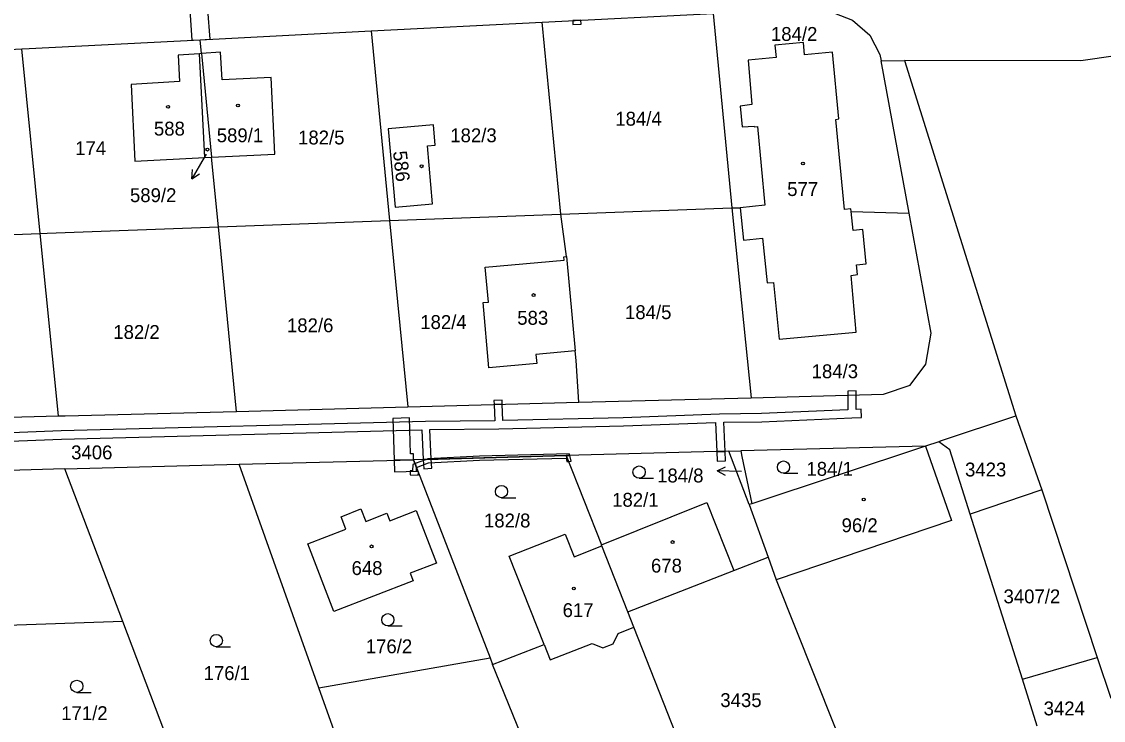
# Model space of a CAD drawing. Extents: x -776734 to -748832, y -1118122 to -976986.
# Drawn here: x -753177.2 to -753044.6, y -1115523.5 to -1115437.8 of the extents above; entities that cross this region are included whole.
import ezdxf

# ---------------------------------------------------------------- set-up
doc = ezdxf.new("R2010")
doc.units = 0
for name, color, linetype in [('KM_Hranice parcel', 7, 'Continuous'), ('KM_Parcelní čísla', 7, 'Continuous'), ('KM_Pop  PČ popisy', 7, 'Continuous'), ('KM_Vnitřní kresba', 7, 'Continuous'), ('KM_Věcná břemena k části', 7, 'Continuous'), ('KM_Značky budov', 7, 'Continuous'), ('KM_Značky kultur', 7, 'Continuous')]:
    doc.layers.add(name, color=color, linetype=linetype)

msp = doc.modelspace()

# ---------------------------------------------------------------- linework, layer by layer
at = {"layer": 'KM_Hranice parcel'}
for p, q in [((-753113.36, -1115437.88), (-753092.39, -1115436.81)), ((-753092.39, -1115436.81), (-753090.09, -1115460.62)), ((-753134.33, -1115438.96), (-753113.36, -1115437.88)), ((-753111.08, -1115461.4), (-753113.36, -1115437.88)), ((-753155.3, -1115440.03), (-753134.33, -1115438.96)), ((-753134.33, -1115438.96), (-753132.07, -1115462.19)), ((-753155.13, -1115441.73), (-753155.3, -1115440.03)), ((-753174.89, -1115463.79), (-753177.13, -1115441.15)), ((-753155.13, -1115441.73), (-753155.38, -1115441.75)), ((-753154.7, -1115454.48), (-753155.38, -1115441.75)), ((-753155.13, -1115441.73), (-753153.89, -1115454.44)), ((-753071.8, -1115442.63), (-753068.92, -1115442.57)), ((-753068.37, -1115461.3), (-753071.8, -1115442.63)), ((-753068.92, -1115442.57), (-753055.28, -1115486.14)), ((-753154.7, -1115454.48), (-753153.89, -1115454.44)), ((-753153.05, -1115462.97), (-753153.89, -1115454.44)), ((-753111.08, -1115461.4), (-753090.09, -1115460.62)), ((-753090.09, -1115460.62), (-753089.08, -1115460.62)), ((-753090.09, -1115460.62), (-753087.75, -1115483.91)), ((-753153.05, -1115462.97), (-753132.07, -1115462.19)), ((-753132.07, -1115462.19), (-753111.08, -1115461.4)), ((-753132.07, -1115462.19), (-753129.84, -1115485.02)), ((-753110.37, -1115466.62), (-753111.08, -1115461.4)), ((-753075.47, -1115461.08), (-753068.37, -1115461.3)), ((-753150.83, -1115485.58), (-753153.05, -1115462.97)), ((-753172.67, -1115486.15), (-753174.89, -1115463.79)), ((-753110.37, -1115466.62), (-753109.33, -1115478.16)), ((-753129.84, -1115485.02), (-753108.85, -1115484.47)), ((-753108.85, -1115484.47), (-753087.75, -1115483.91)), ((-753150.83, -1115485.58), (-753129.84, -1115485.02)), ((-753064.52, -1115489.21), (-753055.28, -1115486.14)), ((-753055.28, -1115486.14), (-753052.1, -1115495.21)), ((-753194.82, -1115486.74), (-753172.67, -1115486.15)), ((-753066.38, -1115489.83), (-753088.99, -1115490.44)), ((-753066.38, -1115489.83), (-753087.67, -1115496.9)), ((-753064.73, -1115489.32), (-753066.38, -1115489.83)), ((-753064.73, -1115489.32), (-753064.52, -1115489.21)), ((-753110.4, -1115491.01), (-753129.13, -1115491.51)), ((-753090.47, -1115490.48), (-753110.4, -1115491.01)), ((-753110.4, -1115491.01), (-753106.1, -1115501.92)), ((-753090.47, -1115490.48), (-753088.99, -1115490.44)), ((-753087.97, -1115497), (-753090.47, -1115490.48)), ((-753171.88, -1115492.64), (-753191.76, -1115493.16)), ((-753171.88, -1115492.64), (-753150.49, -1115492.07)), ((-753164.78, -1115511.33), (-753171.88, -1115492.64)), ((-753150.49, -1115492.07), (-753129.13, -1115491.51)), ((-753140.72, -1115519.45), (-753150.49, -1115492.07)), ((-753129.13, -1115491.51), (-753119.75, -1115515.79)), ((-753052.1, -1115495.21), (-753060.88, -1115498.18)), ((-753052.1, -1115495.21), (-753045.31, -1115515.73)), ((-753106.1, -1115501.92), (-753093.16, -1115496.77)), ((-753093.16, -1115496.77), (-753089.86, -1115505.08)), ((-753087.67, -1115496.9), (-753087.97, -1115497)), ((-753087.97, -1115497), (-753085.67, -1115503.45)), ((-753106.04, -1115502.07), (-753106.1, -1115501.92)), ((-753102.86, -1115510.15), (-753106.04, -1115502.07)), ((-753089.86, -1115505.08), (-753085.67, -1115503.45)), ((-753102.86, -1115510.15), (-753089.86, -1115505.08)), ((-753164.78, -1115511.33), (-753182.77, -1115511.96)), ((-753158.06, -1115529.01), (-753164.78, -1115511.33)), ((-753102.12, -1115512.03), (-753102.86, -1115510.15)), ((-753092.24, -1115537.11), (-753102.12, -1115512.03)), ((-753119.43, -1115516.62), (-753113.12, -1115514.16)), ((-753140.72, -1115519.45), (-753119.75, -1115515.79)), ((-753119.75, -1115515.79), (-753119.43, -1115516.62)), ((-753054.49, -1115518.4), (-753045.31, -1115515.73)), ((-753045.31, -1115515.73), (-753043.66, -1115520.72)), ((-753052.68, -1115524.15), (-753054.49, -1115518.4)), ((-753133.38, -1115540.03), (-753140.72, -1115519.45))]:
    msp.add_line(p, q, dxfattribs=at)
for points in [[(-753092.39, -1115436.81), (-753079.2, -1115436.14), (-753075.33, -1115437.62), (-753073.2, -1115439.48), (-753071.95, -1115441.84), (-753071.8, -1115442.63)], [(-753026.35, -1115439.58), (-753047.32, -1115442.62), (-753068.92, -1115442.57)], [(-753177.13, -1115441.15), (-753176.23, -1115441.1), (-753155.3, -1115440.03)], [(-753075.47, -1115461.08), (-753075.5, -1115460.75), (-753076.29, -1115460.83), (-753077.35, -1115449.8), (-753076.97, -1115449.72), (-753077.77, -1115441.56), (-753081.19, -1115441.9), (-753081.33, -1115440.36), (-753084.82, -1115440.72), (-753084.67, -1115442.23), (-753088.12, -1115442.56), (-753087.64, -1115447.99), (-753089.09, -1115448.18), (-753088.82, -1115450.7), (-753087.37, -1115450.62), (-753087.33, -1115450.72), (-753086.98, -1115450.69), (-753086.07, -1115460.3), (-753089.08, -1115460.62)], [(-753199.25, -1115442.28), (-753197.75, -1115442.2), (-753177.13, -1115441.15)], [(-753155.38, -1115441.75), (-753157.97, -1115441.92), (-753157.8, -1115445.17), (-753163.76, -1115445.52), (-753163.28, -1115454.91), (-753154.7, -1115454.48)], [(-753153.89, -1115454.44), (-753146.13, -1115454.06), (-753146.59, -1115444.66), (-753152.6, -1115444.96), (-753152.78, -1115441.58), (-753155.13, -1115441.73)], [(-753126.47, -1115452.96), (-753126.68, -1115450.46), (-753132.24, -1115450.95), (-753131.36, -1115460.56), (-753126.81, -1115460.16), (-753127.43, -1115453.05), (-753126.47, -1115452.96)], [(-753089.08, -1115460.62), (-753088.68, -1115464.59), (-753086.36, -1115464.36), (-753085.77, -1115469.85), (-753084.99, -1115469.79), (-753084.31, -1115476.75), (-753074.85, -1115475.86), (-753075.49, -1115468.92), (-753074.71, -1115468.81), (-753074.81, -1115467.64), (-753073.64, -1115467.49), (-753074.05, -1115463.3), (-753075.24, -1115463.42), (-753075.47, -1115461.08)], [(-753087.75, -1115483.91), (-753071.51, -1115483.48), (-753068.24, -1115482.37), (-753066.33, -1115479.78), (-753065.66, -1115475.98), (-753068.37, -1115461.3)], [(-753174.89, -1115463.79), (-753174.04, -1115463.76), (-753153.05, -1115462.97)], [(-753197.02, -1115464.62), (-753195.52, -1115464.56), (-753174.89, -1115463.79)], [(-753109.33, -1115478.16), (-753114.14, -1115478.61), (-753114.03, -1115479.73), (-753119.88, -1115480.23), (-753120.6, -1115472.25), (-753119.94, -1115472.2), (-753120.34, -1115467.92), (-753110.67, -1115467.05), (-753110.7, -1115466.65), (-753110.37, -1115466.62)], [(-753108.85, -1115484.47), (-753109.21, -1115479.33), (-753109.33, -1115478.16)], [(-753172.67, -1115486.15), (-753171.82, -1115486.13), (-753150.83, -1115485.58)], [(-753060.88, -1115498.18), (-753063.37, -1115490.29), (-753064.73, -1115489.32)], [(-753088.99, -1115490.44), (-753088.86, -1115491.13), (-753087.67, -1115496.9)], [(-753126.33, -1115504.18), (-753129.55, -1115505.43), (-753129.18, -1115506.36), (-753138.89, -1115510.12), (-753142.1, -1115501.82), (-753137.44, -1115500), (-753138.01, -1115498.51), (-753135.59, -1115497.52), (-753134.98, -1115499.07), (-753132.4, -1115498.06), (-753132.04, -1115498.99), (-753128.82, -1115497.74), (-753126.33, -1115504.18)], [(-753054.49, -1115518.4), (-753059.4, -1115502.85), (-753060.88, -1115498.18)], [(-753113.12, -1115514.16), (-753117.39, -1115503.33), (-753110.53, -1115500.62), (-753109.42, -1115503.4), (-753106.04, -1115502.07)], [(-753085.67, -1115503.45), (-753084.67, -1115506.24), (-753075.29, -1115529.81), (-753075.57, -1115529.91), (-753075.03, -1115531.47)], [(-753113.12, -1115514.16), (-753112.38, -1115516.05), (-753107.22, -1115514.03), (-753105.91, -1115514.56), (-753104.66, -1115514.09), (-753104.05, -1115512.8), (-753102.12, -1115512.03)], [(-753111.11, -1115537.1), (-753119.01, -1115517.7), (-753119.43, -1115516.62)]]:
    msp.add_lwpolyline(points, dxfattribs=at)
at = {"layer": 'KM_Pop  PČ popisy'}
for p, q in [((-753154.56, -1115454.05), (-753154.81, -1115454.48)), ((-753154.81, -1115454.48), (-753156.31, -1115457.079)), ((-753156.31, -1115457.079), (-753156.243, -1115455.961)), ((-753156.31, -1115457.079), (-753155.376, -1115456.462)), ((-753091.919, -1115492.865), (-753090.901, -1115492.4)), ((-753088.92, -1115492.97), (-753091.919, -1115492.865)), ((-753091.919, -1115492.865), (-753090.936, -1115493.401))]:
    msp.add_line(p, q, dxfattribs=at)
at = {"layer": 'KM_Vnitřní kresba'}
for p, q in [((-753066.38, -1115489.83), (-753063.18, -1115498.96)), ((-753063.18, -1115498.96), (-753084.67, -1115506.24))]:
    msp.add_line(p, q, dxfattribs=at)
at = {"layer": 'KM_Věcná břemena k části'}
for points in [[(-753156.54, -1115436.43), (-753156.29, -1115440.08), (-753155.3, -1115440.03), (-753154.04, -1115439.97), (-753154.33, -1115436.36)], [(-753253.5, -1115437.29), (-753253.56, -1115438.69), (-753253.67, -1115441.34), (-753253.19, -1115453.81), (-753250.94, -1115463.24), (-753250.06, -1115465.79), (-753246.79, -1115471.03), (-753249.27, -1115473), (-753248.76, -1115473.87), (-753246.24, -1115471.86), (-753242.45, -1115477.33), (-753238.26, -1115481.7), (-753236.4, -1115483.2), (-753232.56, -1115485.32), (-753227.88, -1115487.3), (-753219.89, -1115489.22), (-753206.07, -1115490.3), (-753195.28, -1115489.87), (-753172.28, -1115488.98), (-753128.12, -1115487.85), (-753127.94, -1115491.48), (-753126.95, -1115491.45), (-753127.13, -1115487.82), (-753118.66, -1115487.72)], [(-753074.21, -1115486.32), (-753074.27, -1115485.32), (-753074.87, -1115485.36), (-753074.87, -1115483.57), (-753074.87, -1115483.07), (-753075.87, -1115483.1), (-753075.87, -1115483.6), (-753075.87, -1115485.41), (-753086.48, -1115485.85), (-753091.63, -1115485.92), (-753103.43, -1115486.37), (-753118.17, -1115486.71), (-753118.26, -1115484.72), (-753119.26, -1115484.74), (-753119.18, -1115486.73), (-753127.66, -1115486.83), (-753172.34, -1115487.98), (-753194.76, -1115488.85)], [(-753118.66, -1115487.72), (-753103.37, -1115487.37), (-753092.1, -1115486.94), (-753091.94, -1115490.52), (-753090.94, -1115490.49), (-753091.1, -1115486.91), (-753086.43, -1115486.85), (-753075.41, -1115486.39), (-753074.21, -1115486.32)]]:
    msp.add_lwpolyline(points, dxfattribs=at)
for points in [[(-753109.61, -1115437.69), (-753109.59, -1115438.19), (-753108.59, -1115438.14), (-753108.61, -1115437.64)], [(-753119.26, -1115484.74), (-753118.26, -1115484.72), (-753118.28, -1115484.22), (-753119.28, -1115484.24)], [(-753131.52, -1115491.57), (-753129.13, -1115491.51), (-753129.15, -1115490.78), (-753129.5, -1115490.79), (-753129.62, -1115486.38), (-753131.65, -1115486.44)], [(-753127.29, -1115491.91), (-753121.04, -1115491.57), (-753110.43, -1115491.31), (-753110.34, -1115491.72), (-753110.12, -1115491.71), (-753110.4, -1115491.01), (-753127.54, -1115491.47), (-753128.94, -1115491.99), (-753128.75, -1115492.49), (-753128.75, -1115492.46)], [(-753126.95, -1115491.45), (-753127.94, -1115491.48), (-753127.88, -1115492.61), (-753126.89, -1115492.56)], [(-753110.03, -1115490.79), (-753121.06, -1115491.07), (-753127.39, -1115491.41), (-753127.54, -1115491.47), (-753110.4, -1115491.01), (-753109.98, -1115491)], [(-753109.98, -1115491), (-753110.4, -1115491.01), (-753110.12, -1115491.71), (-753109.82, -1115491.7)], [(-753090.94, -1115490.49), (-753091.94, -1115490.52), (-753091.89, -1115491.69), (-753090.89, -1115491.65)], [(-753131.52, -1115491.57), (-753131.48, -1115492.98), (-753128.59, -1115492.9), (-753129.13, -1115491.51)], [(-753129.52, -1115492.86), (-753129.54, -1115493.35), (-753128.55, -1115493.4), (-753128.53, -1115493.06), (-753128.59, -1115492.9), (-753128.77, -1115492.89), (-753128.75, -1115492.49), (-753128.94, -1115491.99), (-753129.23, -1115492.1), (-753129.27, -1115492.87)]]:
    msp.add_lwpolyline(points, close=True, dxfattribs=at)
at = {"layer": 'KM_Značky budov'}
for centre in [(-753159.2268, -1115448.2692), (-753150.6468, -1115448.0992), (-753154.3968, -1115453.4992), (-753128.1368, -1115455.5492), (-753081.3868, -1115455.1992), (-753114.4068, -1115471.3292), (-753073.9368, -1115496.3892), (-753134.2668, -1115502.1292), (-753097.3668, -1115501.5992), (-753109.4668, -1115507.2892)]:
    msp.add_circle(centre, 0.175, dxfattribs=at)
at = {"layer": 'KM_Značky kultur'}
for p, q in [((-753101.473, -1115493.77), (-753099.723, -1115493.77)), ((-753083.773, -1115493.16), (-753082.023, -1115493.16)), ((-753118.343, -1115496.17), (-753116.593, -1115496.17)), ((-753132.283, -1115511.87), (-753130.533, -1115511.87)), ((-753153.303, -1115514.43), (-753151.553, -1115514.43)), ((-753170.413, -1115520.03), (-753168.663, -1115520.03))]:
    msp.add_line(p, q, dxfattribs=at)
for centre in [(-753101.4729, -1115493.0198), (-753083.7729, -1115492.4098), (-753118.3429, -1115495.4198), (-753132.2829, -1115511.1198), (-753153.3029, -1115513.6798), (-753170.4129, -1115519.2798)]:
    msp.add_circle(centre, 0.75, dxfattribs=at)

# ---------------------------------------------------------------- texts
at = {"layer": 'KM_Parcelní čísla'}
for s, p in [('184/2', (-753085.31, -1115440.18)), ('184/4', (-753104.39, -1115450.57)), ('588', (-753160.95, -1115451.78)), ('589/1', (-753153.25, -1115452.6)), ('182/5', (-753143.28, -1115452.87)), ('182/3', (-753124.62, -1115452.6)), ('174', (-753170.61, -1115454.18)), ('589/2', (-753163.887, -1115459.938)), ('577', (-753083.32, -1115459.19)), ('184/5', (-753103.2, -1115474.28)), ('182/6', (-753144.64, -1115475.89)), ('182/4', (-753128.3, -1115475.49)), ('583', (-753116.41, -1115474.97)), ('182/2', (-753165.93, -1115476.71)), ('184/3', (-753080.32, -1115481.52)), ('3406', (-753171.1, -1115491.46)), ('184/8', (-753099.267, -1115494.294)), ('184/1', (-753080.96, -1115493.48)), ('3423', (-753061.514, -1115493.56)), ('182/1', (-753104.778, -1115497.27)), ('182/8', (-753120.49, -1115499.81)), ('96/2', (-753076.65, -1115500.39)), ('648', (-753136.725, -1115505.64)), ('678', (-753100.015, -1115505.34)), ('3407/2', (-753056.8, -1115509.11)), ('617', (-753110.85, -1115510.79)), ('176/2', (-753134.98, -1115515.23)), ('176/1', (-753154.86, -1115518.51)), ('3435', (-753091.514, -1115521.82)), ('171/2', (-753172.32, -1115523.42)), ('3424', (-753051.884, -1115522.84))]:
    msp.add_text(s, height=1.7, dxfattribs=at).set_placement(p)
msp.add_text('586', height=1.7, rotation=275.999997, dxfattribs=at).set_placement((-753131.645, -1115453.738))

doc.saveas('drawing.dxf')
